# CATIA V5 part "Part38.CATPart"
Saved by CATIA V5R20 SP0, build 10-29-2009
Part number: VA 161320-4
Revision: ANY
Definition: UNKNOWN
Nomenclature: VA 161320-4
Source: Unknown
Bounding box of the stored display mesh (mm): x -5.5 to 5.5, y 0 to 5.5, z -5 to 5
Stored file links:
  C:\Users\Utente\Desktop\IO LAVORO\3D X SITO CF\CUMSA\3D files VA\VA 201720\Part38.CATPart
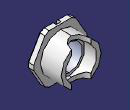
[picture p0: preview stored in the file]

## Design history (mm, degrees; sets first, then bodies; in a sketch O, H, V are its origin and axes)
Body1 "Cortar-Extruir4" (main body)
  Solid1: solid without history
